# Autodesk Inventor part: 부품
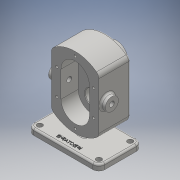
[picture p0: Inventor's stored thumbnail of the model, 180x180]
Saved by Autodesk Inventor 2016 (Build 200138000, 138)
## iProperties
Created: 2019-03
Part Number: 부품
Material: 일반
Document SubType Name: Modeling
Designer: USER
Density: 1 g/cm^3
Appearance: 기본값
Author: USER
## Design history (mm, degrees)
sketch "스케치1"
  geometry: L1 (0, 0)-(120, 0); L2 (120, 0)-(120, 73); L3 (120, 73)-(0, 73); L4 (0, 73)-(0, 0); 1 further point
  constraints: 8 end point, 3 perpendicular, 1 coincident, 1 horizontal
  dimensions: "d0" = 120 distance of L2.end L3.end; "d1" = 73 distance of L1.end L2.end
extrude "돌출1" new body sketch "스케치1" distance "d2" = 10; taper "d3" = 0 deg
node "작업 평면1"
sketch "스케치2"
  geometry: L1 (100, -33.279)-(100, -122.721); L2 (20, -122.721)-(20, -33.279); L3 (0, 0)-(120, 0) reference; L4 (20, -78)-(100, -78); A1 r 60 centre (60, -78) between (20, -122.721) and (100, -122.721); A2 r 60 centre (60, -78) between (100, -33.279) and (20, -33.279); 4 further points
  constraints: 6 end point, 6 point on circle, 5 midpoint, 2 centre point, 2 vertical alignment
  dimensions: "d8" = 78 distance between parallel lines of L3 L4; "d11" = 60 radius of A2; "d15" = 80 distance between parallel lines of L1 L2; "d18" = 60 distance of A1.centre point (60, -138)
extrude "돌출2" join sketch "스케치2" distance "d19" = 53; taper "d20" = 0 deg
fillet "모깎기1" dims "d21" = 10
sketch "스케치3"
  geometry: L1 (36, 100)-(36, 56); L2 (84, 100)-(84, 56); A1 r 24 centre (60, 100) between (84, 100) and (36, 100); A2 r 24 centre (60, 56) between (36, 56) and (84, 56); A3 r 60 centre (60, 78) between (96, 126) and (24, 126) reference; A4 r 60 centre (60, 78) between (24, 30) and (96, 30) reference; 3 further points
  constraints: 6 point on circle, 4 end point, 2 centre point, 2 tangent, 2 vertical alignment
  dimensions: "d22" = 48 diameter of A1; "d23" = 48 diameter of A2; "d24" = 22 distance of A3.centre A1.centre; "d25" = 22 distance of A3.centre A2.centre; "d26" = 44 distance of L2.start L2.end; "d27" = 44 distance of L1.start L1.end
extrude "돌출3" cut sketch "스케치3" distance "d28" = 29; taper "d29" = 0 deg
sketch "스케치4"
  geometry: C1 r 19 at (60, -100); A1 r 60 centre (60, -78) between (24, -126) and (96, -126) reference; 2 further points
  constraints: 1 centre point, 1 point on circle, 1 vertical alignment
  dimensions: "d30" = 38 diameter of C1; "d31" = 22 distance of A1.centre C1.centre
extrude "돌출4" join sketch "스케치4" distance "d32" = 17; taper "d33" = 0 deg
fillet "모깎기2" dims "d34" = 3
node "작업 평면2"
sketch "스케치5"
  geometry: L1 (18, -106.272)-(18, 82.806); L2 (118, 0)-(118, -73) reference; L3 (5.5, -9)-(9.5, -9); L4 (9.5, -9)-(9.5, 9.7); L5 (9.5, 9.7)-(4, 9.7); L6 (37, 17)-(-1, 17) reference; L7 (3.596, 17)-(18, 17); L8 (18, -24)-(-6, -24) reference; L9 (5.5, -24)-(5.5, -9); L10 (5.5, -24)-(18, -24); L11 (18, 17)-(18, -24); L12 (4, 9.7)-(4, 16.3); L13 (4, 16.3)-(3.596, 17); 1 further point
  constraints: 20 end point, 5 point on line, 4 perpendicular, 2 vertical, 1 midpoint
  dimensions: "d35" = 100 distance between parallel lines of L2 L1; "d36" = 15 distance of L9.start L3.start; "d39" = 0 distance between parallel lines of L11 L1; "d40" = 17 diameter of L4 L1; "d41" = 25 diameter of L9 L1; "d52" = 0.7 vertical distance of L12.end L7.start; "d53" = 7.3 distance between parallel lines of L6 L5; "d54" = 28 diameter of L12 L1; "d55" = 30 deg angle of L12 L13
revolve "회전1" sketch "스케치5" stored, may be unused: angle "d43" = 90 deg
sketch "스케치6"
  geometry: C1 r 12.5 at (60, 56); A1 r 60 centre (60, 78) between (96, 126) and (24, 126) reference; 2 further points
  constraints: 1 centre point, 1 point on circle, 1 vertical alignment
  dimensions: "d44" = 25 diameter of C1; "d45" = 22 distance of A1.centre C1.centre
extrude "돌출5" cut sketch "스케치6" distance "d46" = 15; taper "d47" = 0 deg
chamfer "모따기1" distance "d48" = 1; stored, may be unused: second distance "d49" = 2, angle "d50" = 45 deg
fillet "모깎기3" dims "d51" = 0.5
sketch "스케치7"
  geometry: L1 (80, -53)-(0, -53) reference; C1 r 11 at (40, -39); 2 further points
  constraints: 1 centre point, 1 midpoint, 1 vertical alignment
  dimensions: "d56" = 22 diameter of C1; "d57" = 14 distance from line of L1 C1.centre
extrude "돌출6" join sketch "스케치7" distance "d58" = 8; taper "d59" = 0 deg
sketch "스케치8"
  geometry: L1 (80, -53)-(0, -53) reference; C1 r 11 at (40, -39); 2 further points
  constraints: 1 centre point, 1 midpoint, 1 vertical alignment
  dimensions: "d60" = 22 diameter of C1; "d61" = 14 distance from line of L1 C1.centre
extrude "돌출7" join sketch "스케치8" distance "d62" = 8; taper "d63" = 0 deg
fillet "모깎기4" dims "d64" = 3
sketch "스케치9"
  geometry: C1 r 11 at (0, 0) reference; 2 further points
  constraints: 1 coincident
hole "구멍1" sketch "스케치9" at (0, 0) diameter "d65" = 8.376; stored, may be unused: countersink angle "d69" = 90 deg, drill point angle "d71" = 0 deg; dims "d66" = 100, "d67" = 4, "d68" = 2, "d70" = 27.3
sketch "스케치10"
  geometry: C1 r 12.5 at (60, 100) reference; C2 r 8.5 at (60, 100) reference; C3 r 12.5 at (60, 56) reference; 7 further points
  constraints: 2 horizontal alignment, 2 vertical alignment
  dimensions: "d74" = 31 distance of C1.centre point (60, 131); "d75" = 31 distance of point (60, 25) C3.centre; "d76" = 44 distance of point (91, 100) point (91, 56); "d77" = 44 distance of point (29, 56) point (29, 100); "d78" = 31 distance of C1.centre point (29, 100); "d79" = 31 distance of C3.centre point (29, 56); "d80" = 31 distance of C3.centre point (91, 56); "d81" = 31 distance of C1.centre point (91, 100)
hole "구멍2" sketch "스케치10" at (60, 131), (60, 25), (91, 56), (91, 100), (29, 100), (29, 56) diameter "d82" = 4.134; stored, may be unused: countersink angle "d86" = 90 deg, drill point angle "d88" = 118 deg; dims "d83" = 10, "d84" = 4, "d85" = 2, "d87" = 12
node "작업 평면3"
sketch "스케치11"
  geometry: L1 (0, 73)-(-10, 73) reference; L2 (-10, 73)-(-10, 30); L3 (-10, 73)-(-10, 0) reference; L4 (-10, 30)-(-19.747, 30); L5 (-19.747, 30)-(-19.747, 73); L6 (-19.747, 73)-(-10, 73); 1 further point
  constraints: 8 end point, 2 perpendicular, 1 horizontal, 1 point on line
  dimensions: "d89" = 43 distance of L4.end L5.end; "d90" = 9.74678 distance between parallel lines of L2 L5
extrude "돌출8" join sketch "스케치11" stored distance "d91" = 12; taper "d92" = 0 deg
fillet "모깎기5" dims "d93" = 3
fillet "모깎기6" dims "d94" = 3
fillet "모깎기7" dims "d95" = 10
fillet "모깎기8" dims "d96" = 3
sketch "스케치12"
  geometry: A1 r 10 centre (10, 63) between (10, 73) and (0, 63) reference; A2 r 10 centre (10, 10) between (0, 10) and (10, 0) reference; A3 r 10 centre (110, 10) between (110, 0) and (120, 10) reference; A4 r 10 centre (110, 63) between (120, 63) and (110, 73) reference; 5 further points
  constraints: 4 coincident
hole "구멍3" sketch "스케치12" at (110, 63), (110, 10), (10, 63), (10, 10) diameter "d97" = 9; stored, may be unused: countersink angle "d101" = 90 deg, drill point angle "d103" = 0 deg; dims "d98" = 10, "d99" = 4, "d100" = 2, "d102" = 12
sketch "스케치13"
  geometry: L1 (0, 63)-(0, 10) reference; L2 (10, 0)-(110, 0) reference; 2 further points
  constraints: 1 other
  dimensions: "d104" = 60 distance from line of L1 point (60, 10); "d105" = 10 distance from line of L2 point (60, 10)
feature "엠보싱1" sketch "스케치13" dims "d0" = 120, "d1" = 73, "d21" = 10, "d106" = 0.5, "d107" = 0
node "솔리드1"
node "투영된 루프1"
other parameters: "d4" = 0
